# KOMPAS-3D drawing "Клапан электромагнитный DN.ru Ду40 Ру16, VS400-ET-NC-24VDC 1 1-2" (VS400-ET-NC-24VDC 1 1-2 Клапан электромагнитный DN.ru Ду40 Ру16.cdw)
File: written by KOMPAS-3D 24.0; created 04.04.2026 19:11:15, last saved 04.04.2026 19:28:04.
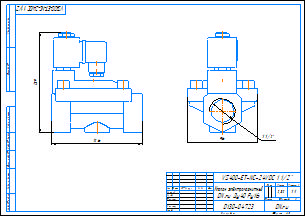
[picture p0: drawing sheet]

Document properties: c3d_UniqueCompID: ef56311e-7521-43dc-8291-0e6108b3d81d; Обозначение: VS400-ET-NC-220VAC 1; Наименование: Клапан электромагнитный DN.ru Ду25 Ру16; Автор: artio; Класс точности: c; Знак неуказанной шероховатости: Шероховатость не задана; Рассекать на разрезах: Да; c3d_UniqueCompID: ef56311e-7521-43dc-8291-0e6108b3d81d; Обозначение: VS400-ET-NC-220VAC 1-2; Наименование: Клапан электромагнитный DN.ru Ду15 Ру16; Автор: artio; Класс точности: c; Знак неуказанной шероховатости: Шероховатость не задана; Рассекать на разрезах: Да; c3d_UniqueCompID: ef56311e-7521-43dc-8291-0e6108b3d81d; Обозначение: VS400-ET-NC-220VAC 3-4; Наименование: Клапан электромагнитный DN.ru Ду20 Ру16; Автор: artio; Класс точности: c; Знак неуказанной шероховатости: Шероховатость не задана; Рассекать на разрезах: Да; c3d_UniqueCompID: ef56311e-7521-43dc-8291-0e6108b3d81d; Обозначение: VS400-ET-NC-220VAC 1 1-4; Наименование: Клапан электромагнитный DN.ru Ду32 Ру16; Автор: artio; Класс точности: c; Знак неуказанной шероховатости: Шероховатость не задана; Рассекать на разрезах: Да; c3d_UniqueCompID: ef56311e-7521-43dc-8291-0e6108b3d81d; Обозначение: VS400-ET-NC-220VAC 3-8; Наименование: Клапан электромагнитный DN.ru Ду10 Ру16; Автор: artio; Класс точности: c; Знак неуказанной шероховатости: Шероховатость не задана; Рассекать на разрезах: Да; c3d_UniqueCompID: ef56311e-7521-43dc-8291-0e6108b3d81d; Обозначение: VS400-ET-NC-220VAC 1 1-2; Наименование: Клапан электромагнитный DN.ru Ду40 Ру16; Автор: artio; Класс точности: c; Знак неуказанной шероховатости: Шероховатость не задана; Рассекать на разрезах: Да; Автор: artio; Форматы листов документа: A3; Полное имя файла: VS400-ET-NC-24VDC 1 1-2 Клапан электромагнитный DN.ru Ду40 Ру16.m3d; Масса: 2.321; Наименование: Клапан электромагнитный DN.ru Ду40 Ру16; Количество листов документа: 1; Примечание: D130-04723

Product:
- Body: Тело 1  | qty 1
    Масса: 4.144257
- Part/product: Клапан электромагнитный DN.ru Ду40 Ру16  | designation VS400-ET-NC-24VDC 1 1-2
    Масса: 2.321
    Раздел спецификации: Прочие изделия
    Примечание: D130-04723
    additional columns: ef56311e-7521-43dc-8291-0e6108b3d81d; VS400-ET-NC-220VAC 1 1-2; artio; c; Шероховатость не задана; Да

Views: Вид 1, Спереди
Referenced files in C:\Users\artio\OneDrive\Рабочий стол\Клапан электромагнитный DN.ru\VS400-ET-NC\VS400-ET-NC-24VDC\: VS400-ET-NC-24VDC 3-8 Клапан электромагнитный DN.ru Ду10 Ру16.m3d, VS400-ET-NC-24VDC 1 1-2 Клапан электромагнитный DN.ru Ду40 Ру16.m3d
Referenced files in C:\Users\artio\OneDrive\Рабочий стол\Клапан электромагнитный DN.ru\VS400-ET-NC\: VS400-ET-NC-24VDC 3-8 Клапан электромагнитный DN.ru Ду10 Ру16.cdw
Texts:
  VS400-ET-NC-24VDC 1 1-2
  Клапан электромагнитный
  DN.ru Ду40 Ру16
  VS400-ET-NC-24VDC 1 1/2"
  VS400-ET-NC-24VDC 1 1/2"-
  Клапан электромагнитный DN.ru Ду40 Ру16
  VS400-ET-NC-24VDC 1 1-2 Клапан электромагнитный DN.ru Ду40 Ру16
Dimensions and other numbers on the sheet: 0; 3; 2; 4; 96; 1 1/2"; 1:1; 1; 2,32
